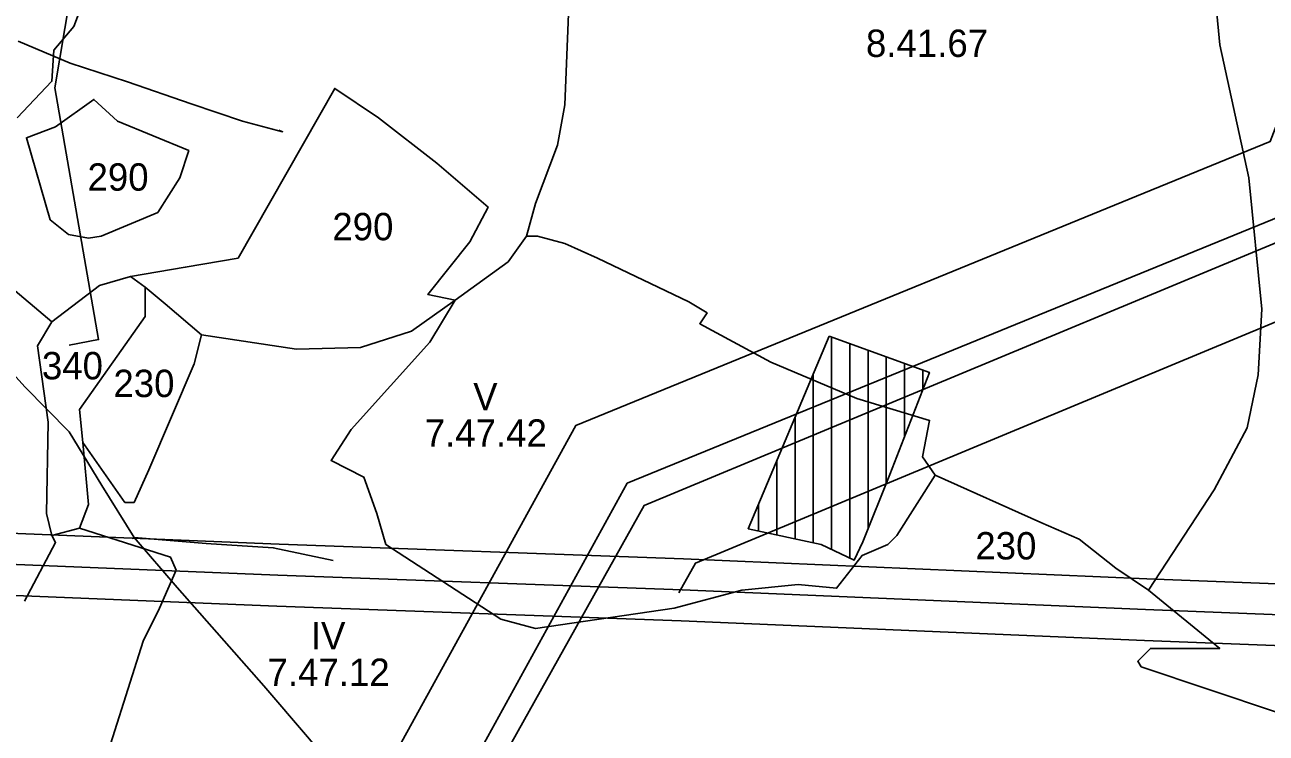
# Model space of a CAD drawing. Extents: x -694504 to -690518, y -983661 to -978958.
# Drawn here: x -692057 to -691377, y -982051 to -981663 of the extents above; entities that cross this region are included whole.
import ezdxf

# ---------------------------------------------------------------- set-up
doc = ezdxf.new("R2010")
doc.units = 0
for name, color, linetype in [('bezpečnostní pásmo', 7, 'Continuous'), ('BPEJ', 7, 'Continuous'), ('ochranné pásmo dálkového kabelu', 7, 'Continuous'), ('ochranné pásmo vedení', 7, 'Continuous'), ('odvodněné pozemky', 7, 'Continuous'), ('třídy přednosti v ochraně ZP', 7, 'Continuous'), ('vedení NN', 7, 'Continuous'), ('vedení VVN 110kV', 7, 'Continuous'), ('VTL plynovod', 7, 'Continuous')]:
    doc.layers.add(name, color=color, linetype=linetype)

msp = doc.modelspace()

# ---------------------------------------------------------------- linework, layer by layer
at = {"layer": 'bezpečnostní pásmo'}
for points in [[(-690673.66, -980441.7), (-690734.35, -980570.76), (-690734.36, -980570.79), (-691030.94, -980978.39), (-691232.87, -981356.8), (-691374.75, -981726.96), (-691755.33, -981882.59), (-691867.86, -982087.1), (-691866.45, -982152.07)], [(-691698.81, -981974.25), (-691698.81, -981974.25), (-691689.76, -981958.05), (-691300.16, -981795.97), (-691146.32, -981397.88), (-690951.91, -981030.3), (-690689.08, -980666.73), (-690682.05, -980670.72), (-690598.61, -980500.09)]]:
    msp.add_lwpolyline(points, dxfattribs=at)
at = {"layer": 'BPEJ'}
for points in [[(-692015.4, -981623.81), (-692030.4, -981663.81), (-692041.4, -981676.81), (-692042.4, -981693.81), (-692061.4, -981713.81)], [(-692061.4, -981713.81), (-692042.4, -981693.81), (-692041.4, -981676.81), (-692030.4, -981663.81), (-692015.4, -981623.81)], [(-691371.4, -982039.81), (-691445.4, -982014.81), (-691447.4, -982011.81), (-691440.4, -982004.81), (-691402.4, -982004.81), (-691441.4, -981972.81), (-691405.4, -981917.81), (-691387.4, -981883.81), (-691381.4, -981854.81), (-691379.4, -981818.81), (-691386.4, -981746.81), (-691402.4, -981673.81), (-691404.4, -981652.81), (-691401.4, -981641.81), (-691388.4, -981642.81), (-691375.4, -981649.81)], [(-691759.4, -981656.81), (-691761.4, -981706.81), (-691765.4, -981728.81), (-691777.4, -981760.81), (-691782.4, -981778.81), (-691792.4, -981792.81), (-691821.4, -981813.81), (-691836.4, -981810.81), (-691813.4, -981781.81), (-691803.4, -981762.81), (-691831.4, -981738.81), (-691863.4, -981713.81), (-691887.4, -981697.81), (-691940.4, -981790.81), (-691969.4, -981795.81), (-691999.4, -981800.81), (-692016.4, -981805.81), (-692042.4, -981825.81), (-692067.4, -981804.81)], [(-691404.4, -981652.81), (-691402.4, -981673.81), (-691386.4, -981746.81), (-691379.4, -981818.81), (-691381.4, -981854.81), (-691387.4, -981883.81), (-691405.4, -981917.81), (-691441.4, -981972.81), (-691459.4, -981960.81), (-691479.4, -981944.81), (-691500.4, -981935.81), (-691558.4, -981909.81), (-691565.4, -981899.81), (-691561.4, -981879.81), (-691601.4, -981867.81), (-691648.4, -981847.81), (-691687.4, -981826.81), (-691683.4, -981820.81), (-691693.4, -981814.81), (-691743.4, -981790.81), (-691761.4, -981782.81), (-691776.4, -981778.81), (-691782.4, -981778.81), (-691777.4, -981760.81), (-691765.4, -981728.81), (-691761.4, -981706.81), (-691759.4, -981656.81)], [(-692067.4, -981804.81), (-692042.4, -981825.81), (-692050.4, -981838.81), (-692044.4, -981880.81), (-692045.4, -981930.81), (-692042.4, -981942.81), (-692040.4, -981946.81), (-692057.4, -981978.81)], [(-692027.4, -981938.81), (-691977.4, -981954.81), (-691974.4, -981961.81), (-691983.4, -981982.81), (-691992.4, -982000.81), (-692017.4, -982079.81), (-692030.4, -982076.81), (-692080.4, -982049.81), (-692093.4, -982082.81), (-692129.4, -982276.81), (-692124.4, -982356.81), (-692107.4, -982425.81), (-692111.4, -982452.81), (-692121.4, -982461.81), (-692155.4, -982469.81), (-692162.4, -982482.81), (-692166.4, -982506.81), (-692184.4, -982528.81), (-692202.4, -982555.81), (-692199.4, -982563.81)]]:
    msp.add_lwpolyline(points, dxfattribs=at)
for points in [[(-691821.4, -981813.81), (-691845.4, -981830.81), (-691873.4, -981839.81), (-691908.4, -981840.81), (-691960.4, -981832.81), (-691980.4, -981815.81), (-691991.4, -981806.81), (-691999.4, -981800.81), (-691969.4, -981795.81), (-691940.4, -981790.81), (-691887.4, -981697.81), (-691863.4, -981713.81), (-691831.4, -981738.81), (-691803.4, -981762.81), (-691813.4, -981781.81), (-691836.4, -981810.81), (-691821.4, -981813.81)], [(-692015.4, -981778.81), (-691984.4, -981765.81), (-691972.4, -981746.81), (-691967.4, -981731.81), (-692006.4, -981715.81), (-692019.4, -981703.81), (-692040.4, -981718.81), (-692056.4, -981724.81), (-692043.4, -981769.81), (-692033.4, -981777.81), (-692022.4, -981779.81), (-692015.4, -981778.81)], [(-691558.4, -981909.81), (-691579.4, -981942.81), (-691584.4, -981947.81), (-691598.4, -981953.81), (-691612.4, -981971.81), (-691633.4, -981969.81), (-691664.4, -981972.81), (-691701.4, -981982.81), (-691777.4, -981993.81), (-691796.4, -981988.81), (-691859.4, -981947.81), (-691864.4, -981930.81), (-691871.4, -981910.81), (-691889.4, -981901.81), (-691878.4, -981884.81), (-691835.4, -981836.81), (-691821.4, -981813.81), (-691792.4, -981792.81), (-691782.4, -981778.81), (-691776.4, -981778.81), (-691761.4, -981782.81), (-691743.4, -981790.81), (-691693.4, -981814.81), (-691683.4, -981820.81), (-691687.4, -981826.81), (-691648.4, -981847.81), (-691601.4, -981867.81), (-691561.4, -981879.81), (-691565.4, -981899.81), (-691558.4, -981909.81)], [(-691991.4, -981806.81), (-691991.4, -981822.81), (-692027.4, -981873.81), (-692025.4, -981891.81), (-692022.4, -981925.81), (-692027.4, -981938.81), (-692042.4, -981942.81), (-692045.4, -981930.81), (-692044.4, -981880.81), (-692050.4, -981838.81), (-692042.4, -981825.81), (-692016.4, -981805.81), (-691999.4, -981800.81), (-691991.4, -981806.81)], [(-691960.4, -981832.81), (-691964.4, -981848.81), (-691989.4, -981906.81), (-691997.4, -981924.81), (-692002.4, -981924.81), (-692025.4, -981891.81), (-692027.4, -981873.81), (-691991.4, -981822.81), (-691991.4, -981806.81), (-691980.4, -981815.81), (-691960.4, -981832.81)]]:
    msp.add_lwpolyline(points, close=True, dxfattribs=at)
at = {"layer": 'ochranné pásmo dálkového kabelu'}
msp.add_lwpolyline([(-691386.18, -980026.89), (-691386.18, -980026.89), (-691386.18, -980026.89), (-691386.18, -980026.89), (-691374.89, -980105.48), (-691346.89, -980518.48), (-691469.89, -980660.48), (-691539.89, -980845.48), (-691610.89, -981162.48), (-691809.89, -981375.48), (-691969.89, -981494.48), (-692021.89, -981584.48), (-692040.89, -981697.48), (-692016.89, -981835.48), (-692032.89, -981838.48)], dxfattribs=at)
at = {"layer": 'ochranné pásmo vedení'}
for points in [[(-691047.73, -981981.62), (-691271.22, -981973.14), (-691442.35, -981966.56), (-691696.3, -981955.69), (-691917.9, -981947.67), (-692137.38, -981938.64), (-692397.79, -981927.36), (-692632.57, -981919.04), (-692886.88, -981909.19), (-693061.33, -981902.24)], [(-693056.86, -981936.45), (-692888.21, -981943.16), (-692633.83, -981953.01), (-692399.13, -981961.33), (-692138.82, -981972.61), (-691919.21, -981981.65), (-691697.64, -981989.66), (-691443.73, -982000.53), (-691272.52, -982007.11), (-691049.79, -982015.57)]]:
    msp.add_lwpolyline(points, dxfattribs=at)
at = {"layer": 'odvodněné pozemky'}
for p, q in [((-691615.16, -981950.57), (-691615.16, -981833.98)), ((-691605.16, -981955.32), (-691605.16, -981837.62)), ((-691595.16, -981939.39), (-691595.16, -981841.26)), ((-691585.16, -981914.19), (-691585.16, -981844.89)), ((-691625.16, -981946.91), (-691625.16, -981854.37)), ((-691575.16, -981888.54), (-691575.16, -981848.53)), ((-691565.16, -981862.79), (-691565.16, -981852.17)), ((-691635.16, -981944.75), (-691635.16, -981878.16)), ((-691645.16, -981942.59), (-691645.16, -981901.95)), ((-691655.16, -981940.43), (-691655.16, -981925.73))]:
    msp.add_line(p, q, dxfattribs=at)
for points in [[(-691616.4, -981833.53), (-691660.83, -981939.21), (-691620.94, -981947.83), (-691602.8, -981956.44), (-691597.94, -981946.38)], [(-691597.94, -981946.38), (-691583.3, -981909.49), (-691561.55, -981853.48), (-691616.4, -981833.53)]]:
    msp.add_lwpolyline(points, dxfattribs=at)
at = {"layer": 'vedení NN'}
for points in [[(-692060.84, -981671.79), (-692032.41, -981683.91), (-692001.06, -981694.15), (-691966.1, -981706.21), (-691937.97, -981715.65), (-691916.06, -981721.56), (-691918.14, -981720.74)], [(-692122.86, -981814.39), (-692081.71, -981834.3), (-692057.2, -981861.29), (-692032.92, -981885.97), (-692015.07, -981915.38), (-691997.3, -981943.94)], [(-691998.37, -981944.61), (-691997.3, -981943.94)], [(-691997.3, -981943.94), (-691957.86, -981947.26), (-691921.16, -981949.6), (-691888.23, -981956.6)], [(-691997.3, -981943.94), (-691973.74, -981971.43), (-691926.29, -982025.39), (-691902.34, -982053.27), (-691877.91, -982082.33), (-691876.94, -982081.51)]]:
    msp.add_lwpolyline(points, dxfattribs=at)
at = {"layer": 'vedení VVN 110kV'}
msp.add_lwpolyline([(-693059.68, -981919.32), (-692887.54, -981926.17), (-692633.2, -981936.03), (-692398.46, -981944.34), (-692138.1, -981955.62), (-691918.56, -981964.66), (-691696.97, -981972.67), (-691443.04, -981983.54), (-691271.87, -981990.13), (-691048.23, -981998.61)], dxfattribs=at)
at = {"layer": 'VTL plynovod'}
for points in [[(-691814.08, -982124.64), (-691815.38, -982100.95), (-691717.93, -981926.44), (-691331.31, -981765.6), (-691182.79, -981381.26), (-690985.96, -981009.13), (-690713.32, -980631.99), (-690697.26, -980585.89), (-690644.68, -980474.09)], [(-691827.12, -982121.44), (-691827.64, -982096.98), (-691727.1, -981914.26), (-691343.6, -981757.43), (-691196.41, -981373.44), (-690996.96, -980999.68), (-690711.85, -980607.83), (-690699.31, -980614.95), (-690634.54, -980482.52)]]:
    msp.add_lwpolyline(points, dxfattribs=at)

# ---------------------------------------------------------------- texts
at = {"layer": 'třídy přednosti v ochraně ZP'}
for s, p in [('8.41.67', (-691596.31, -981680.51)), ('290', (-692022.91, -981753.84)), ('290', (-691888.75, -981781.03)), ('340', (-692047.92, -981857.27)), ('230', (-692008.73, -981866.99)), ('V', (-691811.56, -981874.2)), ('7.47.42', (-691838.11, -981894.2)), ('230', (-691536.37, -981956.02)), ('IV', (-691900.53, -982005.36)), ('7.47.12', (-691924.25, -982025.36))]:
    msp.add_text(s, height=15, dxfattribs=at).set_placement(p)

doc.saveas('drawing.dxf')
